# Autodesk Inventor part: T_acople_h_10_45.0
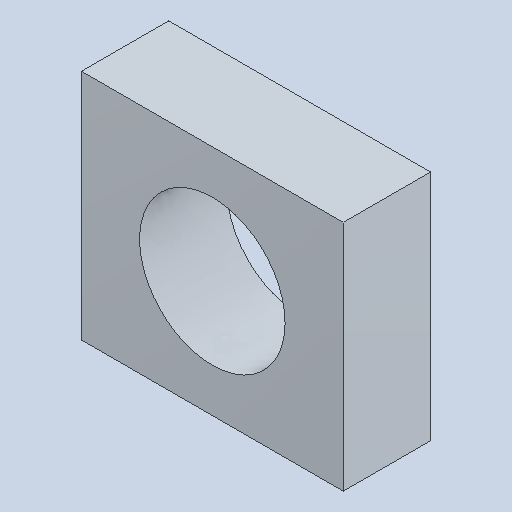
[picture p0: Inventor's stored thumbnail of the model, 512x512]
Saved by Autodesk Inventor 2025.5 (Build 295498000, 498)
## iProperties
Created: 2026-10
Part Number: T_acople_h_10_45.0
Material: Genérico
Document SubType Name: Modeling
Designer: Luis M
Density: 1 g/cm^3
Appearance: Valor por defecto
Author: Luis M
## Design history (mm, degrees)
feature "Base1"
node "Sólido1"
